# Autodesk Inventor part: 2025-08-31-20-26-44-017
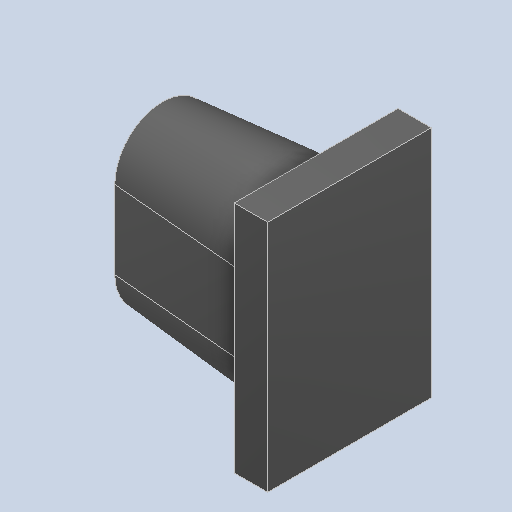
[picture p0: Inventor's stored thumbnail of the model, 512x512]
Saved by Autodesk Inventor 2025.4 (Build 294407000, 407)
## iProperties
Created: 2026-09
Part Number: 2025-08-31-20-26-44-017
Material: Generic
Document SubType Name: Modeling
Designer: AdminForWorker
Density: 1 g/cm^3
Appearance: Default
Title: Component8
Author: AdminForWorker
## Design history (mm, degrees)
feature "Body1"
body "Solid1"
